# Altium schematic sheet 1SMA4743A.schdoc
size 127 x 101 mm
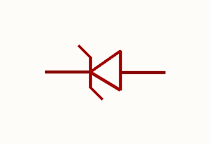
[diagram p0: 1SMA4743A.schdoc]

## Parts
D?  1sma4743a_c364307  [SMA_L4.3-W2.7-LS5.1-RD]  (value not drawn)

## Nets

Not connected (* = marked no-connect by the designer): D? 1 2

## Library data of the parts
D? = 1sma4743a_c364307: 二极管配置:1个独立式;稳压值(标称值):13V;稳压值(范围):12.4V~14.1V;耗散功率(Pd):1W;; Manufacturer: MDD(辰达半导体); AddInBom: yes; ModelId: 5b7d57c23c9f472788911caf890f0710; ModelTransform: 198.4248,106.299,0,0,0,0,0,0,0; Diode Configuration: 1个独立式; Zener Voltage(Nom): 13V; Reverse Leakage Current (Ir): 5uA; Pd - Power Dissipation: 1W; Impedance(Zzt): 10Ω; Operating Junction Temperature Range: -55℃~+150℃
